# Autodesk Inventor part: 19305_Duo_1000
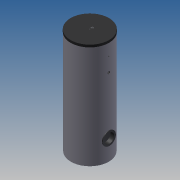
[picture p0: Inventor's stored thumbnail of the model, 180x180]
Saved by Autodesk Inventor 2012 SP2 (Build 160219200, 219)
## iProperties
allow_slope_adjustment: 0 ul
connection_type: 13 ul
flow_configuration2: 1 ul
flow_direction: 2 ul
loss_method: 0 ul
radius: 19,625 mm
description: 0:0:19306_Duo_1000
manufacturer: 0:0:Flamco Group
model: 0:0:Duo 1000
url: 0:0:www.flamcogroup.com
radius: 22,625 mm
Created: 2014-05
Part Number: 19305_Duo_1000
Material: Default
Document SubType Name: Modeling
Designer: michel
Density: 1 g/cm^3
radius: 9,500 mm
radius: 18,295 mm
radius: 12,250 mm
Author: michel
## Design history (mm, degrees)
sketch "Sketch1"
  geometry: C1 r 400 at (0, 0); 1 further point
  constraints: 1 centre point, 1 coincident
  dimensions: "d0" = 800 diameter of C1
extrude "Extrusion1" new body sketch "Sketch1" distance "d1" = 2230; taper "d2" = 0 deg
sketch "Sketch2"
  geometry: L1 (-400, 2230)-(400, 2230) reference; L2 (-400, 0)-(400, 0) reference; L3 (400, 0)-(400, 2230) reference; L4 (400, 2230)-(405, 2230); L5 (405, 2230)-(405, 2180); L6 (405, 2180)-(400, 2180); L7 (400, 2180)-(400, 2230); L8 (0, -394)-(0, 2364) reference; 1 further point
  constraints: 8 end point, 2 parallel, 1 horizontal, 1 perpendicular
  dimensions: "d3" = 5 distance of L5.end L6.end; "d4" = 50 distance of L4.end L5.end
revolve "Revolution1" sketch "Sketch2" stored, may be unused: angle "d5" = 90 deg
workplane "Work Plane1"
workplane "Work Plane2"
workplane "Work Plane3"
workplane "Work Plane4"
workplane "Work Plane5"
workplane "Work Plane6"
workplane "Work Plane11"
workplane "Work Plane12"
sketch "Sketch3"
  geometry: L1 (561.4, 2140)-(-561.4, 2140) reference; L2 (561.4, 1110)-(-561.4, 1110) reference; L3 (561.4, 960)-(-561.4, 960) reference; L4 (561.4, 330)-(-561.4, 330) reference; L5 (561.4, 70)-(-561.4, 70) reference; L6 (400, 0)-(400, 2180) reference; L7 (400, 2140)-(360, 2140); L8 (360, 2140)-(360, 2160.955); L9 (360, 2160.955)-(400, 2160.955); L10 (400, 1110)-(360, 1110); L11 (360, 1110)-(360, 1130.955); L12 (360, 1130.955)-(400, 1130.955); L13 (400, 1130.955)-(400, 1110); L14 (335, 2121.705)-(335, 2119.045); L15 (335, 2119.045)-(401, 2119.045); L16 (401, 2119.045)-(401, 2121.705); L17 (401, 2121.705)-(335, 2121.705); L18 (360, 960)-(360, 973.22); L19 (400, 960)-(360, 960); L20 (360, 973.22)-(400, 973.22); L21 (400, 973.22)-(400, 960); L22 (335, 947.75)-(335, 946.78); L23 (335, 946.78)-(401, 946.78); L24 (401, 946.78)-(401, 947.75); L25 (401, 947.75)-(335, 947.75); L26 (360, 350.955)-(400, 350.955); L27 (360, 330)-(360, 350.955); L28 (400, 330)-(360, 330); L29 (400, 350.955)-(400, 330); L30 (401, 310.375)-(335.165, 310.375); L31 (335.165, 310.375)-(335.165, 309.045); L32 (335.165, 309.045)-(401, 309.045); L33 (401, 309.045)-(401, 310.375); L34 (360, 90.955)-(400, 90.955); L35 (360, 70)-(360, 90.955); L36 (400, 70)-(360, 70); L37 (400, 90.955)-(400, 70); L38 (401, 50.375)-(335, 50.375); L39 (335, 50.375)-(335, 49.045); L40 (335, 49.045)-(401, 49.045); L41 (401, 49.045)-(401, 50.375); L42 (335, 1090.375)-(335, 1089.045); L43 (401, 1089.045)-(401, 1090.375); L44 (401, 1090.375)-(335, 1090.375); L45 (-567, 1930)-(567, 1930) reference; L46 (-567, 1630)-(567, 1630) reference; L47 (-400, 0)-(-400, 2180) reference; L48 (-400, 1930)-(-360, 1930); L49 (-360, 1930)-(-360, 1940.475); L50 (-360, 1940.475)-(-400, 1940.475); L51 (-400, 1940.475)-(-400, 1930); L52 (-401, 1919.525)-(-335, 1919.525); L53 (-335, 1919.525)-(-335, 1920.5); L54 (-335, 1920.5)-(-401, 1920.5); L55 (-401, 1920.5)-(-401, 1919.525); L56 (-400, 1630)-(-335, 1630); L57 (-335, 1630)-(-335, 1653.9); L58 (-335, 1653.9)-(-400, 1653.9); L59 (-400, 1653.9)-(-400, 1630); L60 (-401, 1606.1)-(-335, 1606.1); L61 (-335, 1606.1)-(-335, 1607.375); L62 (-335, 1607.375)-(-401, 1607.375); L63 (-401, 1607.375)-(-401, 1606.1); L64 (400, 2160.955)-(400, 2140)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; 2 further points
  constraints: 112 end point, 16 parallel, 7 horizontal, 7 perpendicular, 6 point on line, 1 collinear
  dimensions: "d19" = 40 distance of L8.end L9.end; "d21" = 40 distance of L11.end L12.end; "d70" = 20.955 distance between parallel lines of L1 L9; "d73" = 40 distance of L18.end L20.end; "d74" = 40 distance of L26.start L26.end; "d75" = 40 distance of L34.start L34.end; "d76" = 13.22 distance between parallel lines of L3 L20; "d85" = 20.955 distance between parallel lines of L2 L12; "d108" = 20.955 distance between parallel lines of L1 L15; "d109" = 2.66 distance between parallel lines of L17 L15; "d110" = 20.955 distance between parallel lines of L10 L12 (= d85); "d113" = 13.22 distance between parallel lines of L19 L20 (= d76); "d114" = 13.22 distance between parallel lines of L23 L3; "d115" = 0.97 distance between parallel lines of L25 L23; "d116" = 20.955 distance between parallel lines of L4 L26; "d117" = 20.955 distance of L26.start L27.start (= d116); "d118" = 20.955 distance between parallel lines of L32 L4; "d119" = 1.33 distance between parallel lines of L30 L32; "d120" = 20.955 distance from line of L34 L35.start (= d121); "d121" = 20.955 distance between parallel lines of L5 L34; "d122" = 20.955 distance between parallel lines of L40 L5; "d123" = 1.33 distance between parallel lines of L38 L40; "d129" = 40 distance of L50.end L49.end; "d130" = 10.475 distance of L49.end L48.end; "d131" = 10.475 distance between parallel lines of L45 L52; "d132" = 0.975 distance between parallel lines of L54 L52; "d134" = 23.9 distance between parallel lines of L46 L58; "d135" = 23.9 distance between parallel lines of L46 L60; "d136" = 1.275 distance between parallel lines of L62 L60; "d154" = 1 distance between parallel lines of L47 L55; "d155" = 1 distance between parallel lines of L47 L63; "d157" = 1 distance between parallel lines of L6 L16; "d158" = 0 distance between parallel lines of L6 L13; "d159" = 1 distance between parallel lines of L6 L43; "d160" = 0 distance between parallel lines of L6 L21; "d161" = 1 distance between parallel lines of L6 L24; "d162" = 0 distance between parallel lines of L6 L29; "d163" = 1 distance between parallel lines of L6 L33; "d164" = 0 distance between parallel lines of L6 L37; "d165" = 1 distance between parallel lines of L6 L41; "d166" = 20.955 distance between parallel lines of L65 L2 (derived); "d167" = 1.33 distance between parallel lines of L44 L65 (derived)
revolve "Revolution2" stored, may be unused: angle "d23" = 90 deg
sketch "Sketch5"
  geometry: L1 (-400, 0)-(-400, 2180) reference; L2 (-400, 0)-(-400, 435); L3 (-220, 435)-(-594, 435); L4 (-400, 435)-(-412.5, 435); L5 (-412.5, 435)-(-412.5, 575); L6 (-412.5, 575)-(-400, 575); L7 (-400, 575)-(-400, 435); L8 (-400, 0)-(400, 0) reference; 1 further point
  constraints: 12 end point, 2 parallel, 2 perpendicular, 1 horizontal, 1 point on line
  dimensions: "d35" = 435 distance of L1.start L2.end; "d36" = 12.5 distance of L5.end L6.end; "d37" = 140 distance of L4.end L5.end; "d124" = 435 distance between parallel lines of L8 L3 (= d35)
revolve "Revolution7" sketch "Sketch5" stored, may be unused: angle "d38" = 90 deg
sketch "Sketch6"
  geometry: C1 r 122.5 at (0, 0); A1 r 140 centre (0, 0) between (140, 0) and (-140, 0) reference; 1 further point
  constraints: 1 centre point, 1 coincident
  dimensions: "d39" = 245 diameter of C1
extrude "Extrusion3" join sketch "Sketch6" stored distance "d40" = 40; taper "d41" = 0 deg
sketch "Sketch7"
  geometry: C1 r 140 at (0, 0) reference; C2 r 102.5 at (0, 0); 1 further point
  constraints: 1 centre point, 1 coincident
  dimensions: "d42" = 205 diameter of C2
extrude "Extrusion4" cut sketch "Sketch7" distance "d43" = 80; taper "d44" = 0 deg
sketch "Sketch15"
  geometry: L1 (-567, 0)-(567, 0) reference; C1 r 20.955 at (0, 50); C2 r 405 at (0, 0) reference; C3 r 10.475 at (0, 0); C4 r 19.625 at (0, 50); C5 r 9.5 at (0, 0)
  constraints: 4 centre point, 3 coincident
  dimensions: "d142" = 41.91 diameter of C1; "d143" = 50 distance from line of L1 C1.centre; "d144" = 20.95 diameter of C3; "d145" = 39.25 diameter of C4; "d146" = 19 diameter of C5
revolve "Revolution9" stored, may be unused: angle "d69" = 90 deg
revolve "Revolution10" stored, may be unused: angle "d92" = 90 deg
revolve "Revolution11" stored, may be unused: angle "d93" = 90 deg
revolve "Revolution12" stored, may be unused: angle "d94" = 90 deg
revolve "Revolution13" stored, may be unused: angle "d95" = 90 deg
revolve "Revolution14" stored, may be unused: angle "d96" = 90 deg
revolve "Revolution15" stored, may be unused: angle "d97" = 90 deg
revolve "Revolution16" stored, may be unused: angle "d98" = 90 deg
revolve "Revolution17" stored, may be unused: angle "d99" = 90 deg
revolve "Revolution18" stored, may be unused: angle "d138" = 90 deg
revolve "Revolution19" stored, may be unused: angle "d139" = 90 deg
revolve "Revolution20" stored, may be unused: angle "d140" = 90 deg
revolve "Revolution21" stored, may be unused: angle "d141" = 90 deg
extrude "Extrusion11" cut sketch "Sketch15" distance "d147" = 40; taper "d148" = 0 deg
extrude "Extrusion12" join sketch "Sketch15" distance "d149" = 2; taper "d150" = 0 deg
body "Solid1"
node "Projected Loop1"
other parameters: "d12" = 0
